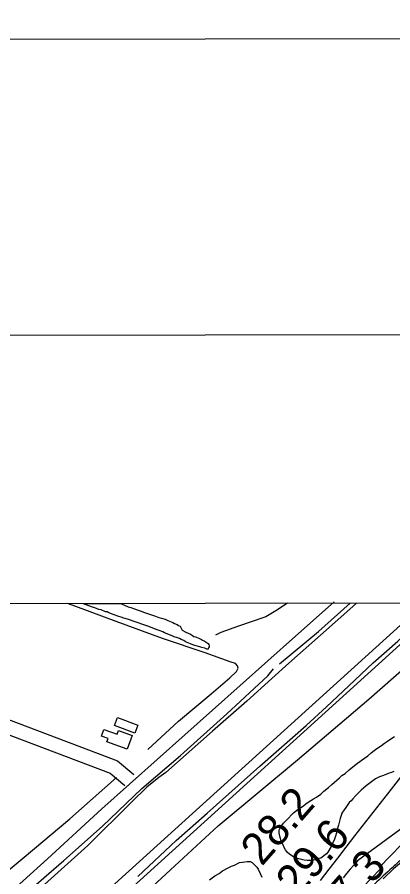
# Model space of a CAD drawing. Extents: x 3324125 to 3362000, y 600753 to 626151.
# Drawn here: x 3334294 to 3335086, y 623752 to 625567 of the extents above; entities that cross this region are included whole.
import ezdxf

# ---------------------------------------------------------------- set-up
doc = ezdxf.new("R2010")
doc.units = 0
for name, color, linetype in [('G-ANNO-NPLT', 7, 'Continuous'), ('V-ANNO-SYMB', 7, 'Continuous'), ('V-BLDG-OTLN', 7, 'Continuous'), ('V-DTCH-CNTR', 7, 'Continuous'), ('V-FLOD-BASE', 7, 'Continuous'), ('V-GRID-FRAM', 7, 'Continuous'), ('V-LEVE-TOET', 7, 'Continuous'), ('V-RIVR-EDGE', 7, 'Continuous'), ('V-RIVR-RANG', 7, 'Continuous'), ('V-ROAD-CNTR', 7, 'Continuous'), ('V-RRAP-RVMT', 7, 'Continuous'), ('V-SITE-VEGE', 7, 'Continuous'), ('V-SURV-LINE', 7, 'Continuous'), ('V-TOPO-MAJR', 7, 'Continuous'), ('V-TOPO-MINR', 7, 'Continuous'), ('V-TOPO-SHOR', 7, 'Continuous')]:
    doc.layers.add(name, color=color, linetype=linetype)

msp = doc.modelspace()

# ---------------------------------------------------------------- linework, layer by layer
at = {"layer": 'G-ANNO-NPLT'}
msp.add_lwpolyline([(3324750.5, 601336.7), (3361417.2, 601400.7), (3361375, 625567.3), (3324708.4, 625503.3)], close=True, dxfattribs=at)
at = {"layer": 'V-ANNO-SYMB'}
msp.add_lwpolyline([(3327499.6, 601966.6), (3360582.7, 602024.3), (3360542.7, 624940.8), (3327459.6, 624883.1), (3327499.6, 601966.6)], dxfattribs=at)
at = {"layer": 'V-BLDG-OTLN'}
for points in [[(3334505.7, 624088.4), (3334548.9, 624072.1), (3334542.6, 624055.7), (3334499.5, 624072)], [(3334526.1, 624021.5), (3334483.4, 624036.9), (3334486, 624044.1), (3334472.1, 624049.1), (3334477.3, 624063.5), (3334505.3, 624053.4), (3334508.1, 624061), (3334536.6, 624050.7)]]:
    msp.add_lwpolyline(points, close=True, dxfattribs=at)
at = {"layer": 'V-DTCH-CNTR'}
msp.add_lwpolyline([(3334864.3, 624329.8), (3334839.5, 624313.6), (3334818.8, 624301), (3334814.7, 624299.6), (3334760.8, 624281.2), (3334723.5, 624268.4), (3334712.4, 624262.8)], dxfattribs=at)
at = {"layer": 'V-FLOD-BASE'}
msp.add_lwpolyline([(3334548.7, 623752.8), (3334629.3, 623828.7), (3334694.8, 623886.6), (3334805.7, 623986), (3334903.7, 624071.5), (3334946.6, 624111.3), (3334993.7, 624155.4), (3335045, 624203.7), (3335097.3, 624249.9), (3335164.8, 624312.5), (3335184.9, 624330.4)], dxfattribs=at)
at = {"layer": 'V-GRID-FRAM'}
msp.add_lwpolyline([(3328210, 624318.2), (3328233.8, 606134.5), (3359834, 606189.7), (3359794.3, 624373.3), (3328210, 624318.2)], dxfattribs=at)
at = {"layer": 'V-LEVE-TOET'}
for points in [[(3335009.6, 624330), (3334995.9, 624317.7), (3334934.1, 624262.2), (3334867.4, 624203.3), (3334831.6, 624171.1), (3334778.9, 624123.1), (3334706, 624059.6), (3334608, 623972.7), (3334592.8, 623961.8), (3334567.6, 623941.3), (3334535.5, 623909.6), (3334443.4, 623818.2), (3334331, 623717.1)], [(3334560.5, 623714.3), (3334617.6, 623766.9), (3334718.3, 623860.2), (3334885.2, 623999.3), (3335035.7, 624127.2), (3335145.4, 624223.5), (3335252.8, 624327.9), (3335255.7, 624330.5)]]:
    msp.add_lwpolyline(points, dxfattribs=at)
at = {"layer": 'V-RIVR-EDGE'}
msp.add_spline([(3335799.7, 624331.4), (3335798.3, 624329.3), (3335794.2, 624318), (3335789.1, 624311.4), (3335780.7, 624303.1), (3335767.1, 624285.2), (3335747.7, 624260.7), (3335731.9, 624240.7), (3335698.2, 624211.1), (3335677.3, 624192.2), (3335662.7, 624176.5), (3335646.5, 624160.8), (3335632.3, 624145.9), (3335615.8, 624131.3), (3335603.3, 624120), (3335592.3, 624106.9), (3335585, 624096.6), (3335578.8, 624094.5), (3335568.5, 624087.9), (3335560.1, 624081), (3335551.6, 624071.1), (3335543.6, 624065.3), (3335538.1, 624063.5), (3335533, 624059.1), (3335530.8, 624053.6), (3335527.8, 624050.7), (3335522.7, 624050), (3335516.1, 624049.7), (3335512.5, 624049.3), (3335497.5, 624037.6), (3335485.4, 624029.3), (3335478.4, 624027.1), (3335472.9, 624023.8), (3335468.5, 624020.5), (3335461.2, 624015.1), (3335455, 624014.4), (3335451.7, 624013.6), (3335449.5, 624010.7), (3335449.5, 624008.2), (3335450.2, 624006.3), (3335449.1, 624003), (3335446.9, 624002.3), (3335438.2, 624001.6), (3335427.5, 623996.9), (3335420.2, 623992.9), (3335409.6, 623985.2), (3335401.9, 623977.9), (3335392.7, 623968.4), (3335375.5, 623956.1), (3335352.8, 623941.9), (3335330.9, 623930.2), (3335312.6, 623925.9), (3335303.4, 623923.7), (3335298.3, 623921.5), (3335294.3, 623916.4), (3335290.6, 623913.9), (3335277.5, 623909.9), (3335265.4, 623904.4), (3335244.1, 623893.5), (3335232.4, 623886.6), (3335209, 623874.2), (3335181.9, 623858.6), (3335164.7, 623847.3), (3335147.9, 623833.1), (3335127, 623810.5), (3335107.2, 623791.5), (3335089.6, 623775.5), (3335053, 623741.5), (3335042, 623729.5), (3335028.8, 623711.3), (3335018.1, 623697.8), (3335015.6, 623695.6), (3335013.4, 623695.2), (3335009, 623694.1), (3335004.6, 623690.5), (3334995.8, 623678.5), (3334991.7, 623671.9), (3334991.4, 623666), (3334990.6, 623658.4), (3334993.5, 623650.7), (3334993.9, 623647.7), (3334996.4, 623642.6), (3334993.1, 623636.8), (3334983.6, 623621.5), (3334967.1, 623601.8), (3334950.9, 623585), (3334929, 623567.9)], degree=3, dxfattribs=at)
at = {"layer": 'V-ROAD-CNTR'}
for points in [[(3334962.6, 624333), (3334881.1, 624260.2), (3334472.9, 623895.9), (3334358, 623790.3), (3334255.1, 623697.1), (3334200.7, 623647.7), (3334152.3, 623600.3), (3334077.2, 623518.6), (3333606.7, 622932.8), (3332948.8, 622115.4), (3332638.7, 621722.9), (3332601.1, 621669.5), (3332582.1, 621643.4), (3332550.9, 621581.9), (3332533.2, 621530.4), (3332516.7, 621467.3), (3332503.8, 621368.2), (3332484.7, 621134.9), (3332435.8, 620389.6)], [(3333436.2, 624344.7), (3333693.9, 624268.2), (3333748.7, 624256.7), (3333781.2, 624250.2), (3333823.7, 624243.1), (3333872.8, 624237.5), (3333917.3, 624219.9), (3334505.5, 623997.4), (3334540.5, 623967.9)], [(3333427.7, 624316), (3333686.6, 624239.1), (3333742.7, 624227.3), (3333775.8, 624220.7), (3333819.5, 624213.3), (3333865.5, 624208.1), (3333906.5, 624191.9), (3334490.1, 623971.2), (3334521.2, 623945)]]:
    msp.add_lwpolyline(points, dxfattribs=at)
at = {"layer": 'V-RRAP-RVMT'}
for p, q in [((3335168.6, 623886.4), (3335057.5, 623771.9)), ((3335060.2, 623769.4), (3334967.1, 623672.5)), ((3335057.5, 623771.9), (3335060.2, 623769.4))]:
    msp.add_line(p, q, dxfattribs=at)
at = {"layer": 'V-SITE-VEGE'}
for p, q in [((3334433.1, 624329), (3334512.9, 624329.2)), ((3334434.2, 624328.7), (3334433.1, 624329)), ((3334445.4, 624324.5), (3334434.2, 624328.7)), ((3334450.7, 624322.4), (3334445.4, 624324.5)), ((3334458.1, 624320.4), (3334450.7, 624322.4)), ((3334466.7, 624316.7), (3334458.1, 624320.4)), ((3334471.5, 624315.7), (3334466.7, 624316.7)), ((3334480.5, 624312), (3334471.5, 624315.7)), ((3334512.9, 624329.2), (3334514.4, 624328.7)), ((3334514.4, 624328.7), (3334528.3, 624322.5)), ((3334528.3, 624322.5), (3334533.6, 624320.9)), ((3334533.6, 624320.9), (3334541.6, 624318.3)), ((3334541.6, 624318.3), (3334547.4, 624316.2)), ((3334547.4, 624316.2), (3334553.8, 624313.6)), ((3334553.8, 624313.6), (3334562.9, 624310.5)), ((3334483.7, 624311.5), (3334480.5, 624312)), ((3334487.4, 624309.4), (3334483.7, 624311.5)), ((3334493.3, 624307.3), (3334487.4, 624309.4)), ((3334497, 624305.8), (3334493.3, 624307.3)), ((3334508.8, 624301.6), (3334497, 624305.8)), ((3334513.5, 624300.6), (3334508.8, 624301.6)), ((3334518.9, 624298.5), (3334513.5, 624300.6)), ((3334526.9, 624296.4), (3334518.9, 624298.5)), ((3334533.3, 624293.8), (3334526.9, 624296.4)), ((3334562.9, 624310.5), (3334569.3, 624308.4)), ((3334569.3, 624308.4), (3334575.7, 624305.8)), ((3334575.7, 624305.8), (3334585.8, 624302.7)), ((3334585.8, 624302.7), (3334593.3, 624300.1)), ((3334593.3, 624300.1), (3334598.6, 624298)), ((3334598.6, 624298), (3334606, 624295.9)), ((3334606, 624295.9), (3334611.9, 624293.3)), ((3334538.6, 624292.2), (3334533.3, 624293.8)), ((3334570, 624281.3), (3334538.6, 624292.2)), ((3334589.2, 624274), (3334570, 624281.3)), ((3334611.9, 624293.3), (3334618.8, 624290.7)), ((3334618.8, 624290.7), (3334622.6, 624289.1)), ((3334622.6, 624289.1), (3334626.3, 624287)), ((3334626.3, 624287), (3334631.6, 624284.9)), ((3334631.6, 624284.9), (3334634.3, 624282.8)), ((3334634.3, 624282.8), (3334638, 624281.3)), ((3334638, 624281.3), (3334642.3, 624273.3)), ((3334594, 624272.4), (3334589.2, 624274)), ((3334601.4, 624269.8), (3334594, 624272.4)), ((3334605.2, 624267.7), (3334601.4, 624269.8)), ((3334621.2, 624260.9), (3334605.2, 624267.7)), ((3334625.4, 624258.9), (3334621.2, 624260.9)), ((3334632.4, 624256.8), (3334625.4, 624258.9)), ((3334642.3, 624273.3), (3334649.8, 624268.6)), ((3334649.8, 624268.6), (3334655.1, 624266.5)), ((3334655.1, 624266.5), (3334659.9, 624264.4)), ((3334659.9, 624264.4), (3334664.2, 624261.8)), ((3334664.2, 624261.8), (3334666.9, 624259.7)), ((3334666.9, 624259.7), (3334670.1, 624259.2)), ((3334670.1, 624259.2), (3334672.2, 624258.1)), ((3334672.2, 624258.1), (3334678.6, 624255.5)), ((3334636.6, 624255.2), (3334632.4, 624256.8)), ((3334640.4, 624253.6), (3334636.6, 624255.2)), ((3334645.7, 624251), (3334640.4, 624253.6)), ((3334649.4, 624248.4), (3334645.7, 624251)), ((3334659.6, 624244.2), (3334649.4, 624248.4)), ((3334664.9, 624242.1), (3334659.6, 624244.2)), ((3334669.1, 624240.6), (3334664.9, 624242.1)), ((3334679.8, 624238), (3334669.1, 624240.6)), ((3334678.6, 624255.5), (3334682.9, 624253.4)), ((3334682.9, 624253.4), (3334685, 624251.8)), ((3334685, 624251.8), (3334688.7, 624250.3)), ((3334688.7, 624250.3), (3334695.1, 624246.6)), ((3334695.1, 624246.6), (3334696.7, 624245)), ((3334696.7, 624245), (3334698.4, 624242.4)), ((3334698.4, 624242.4), (3334698.9, 624240.2)), ((3334698.9, 624240.2), (3334698.9, 624237.6)), ((3334683.5, 624236.4), (3334679.8, 624238)), ((3334689.9, 624234.9), (3334683.5, 624236.4)), ((3334694.2, 624232.8), (3334689.9, 624234.9)), ((3334696.8, 624232.8), (3334694.2, 624232.8)), ((3334697.9, 624235.5), (3334696.8, 624232.8)), ((3334698.9, 624237.6), (3334697.9, 624235.5)), ((3335075, 624038.9), (3335084.5, 624045.3)), ((3335084.5, 624045.3), (3335090.3, 624048.5)), ((3335046.9, 624019), (3335052.8, 624023.3)), ((3335052.8, 624023.3), (3335062.3, 624029.7)), ((3335062.3, 624029.7), (3335069.2, 624034.6)), ((3335069.2, 624034.6), (3335075, 624038.9)), ((3335020, 623998.1), (3335033.7, 624007.8)), ((3335033.7, 624007.8), (3335041.1, 624014.2)), ((3335041.1, 624014.2), (3335046.9, 624019)), ((3334994.6, 623978.2), (3335009.4, 623990)), ((3335009.4, 623990), (3335020, 623998.1)), ((3334979.3, 623965.9), (3334985.7, 623970.2)), ((3334985.7, 623970.2), (3334994.6, 623978.2)), ((3335078.6, 623970.9), (3335070.7, 623967.6)), ((3335083.9, 623972.5), (3335078.6, 623970.9)), ((3335088.7, 623974.7), (3335083.9, 623972.5)), ((3334957.7, 623947.2), (3334974, 623961.1)), ((3334974, 623961.1), (3334979.3, 623965.9)), ((3335050, 623959), (3335030.5, 623944.5)), ((3335058.5, 623963.3), (3335050, 623959)), ((3335064.9, 623965.5), (3335058.5, 623963.3)), ((3335070.7, 623967.6), (3335064.9, 623965.5)), ((3334934.4, 623926.8), (3334940.8, 623932.7)), ((3334940.8, 623932.7), (3334950.8, 623940.7)), ((3334950.8, 623940.7), (3334957.7, 623947.2)), ((3335019.4, 623934.9), (3335008.3, 623923.6)), ((3335024.7, 623939.7), (3335019.4, 623934.9)), ((3335030.5, 623944.5), (3335024.7, 623939.7)), ((3334905.9, 623908.5), (3334913.3, 623913.4)), ((3334913.3, 623913.4), (3334919.1, 623916.6)), ((3334919.1, 623916.6), (3334925.4, 623920.4)), ((3334925.4, 623920.4), (3334934.4, 623926.8)), ((3335002, 623917.2), (3334998.3, 623912.9)), ((3335008.3, 623923.6), (3335002, 623917.2)), ((3334877.3, 623887.6), (3334886.8, 623895.1)), ((3334886.8, 623895.1), (3334895.8, 623900.5)), ((3334895.8, 623900.5), (3334905.9, 623908.5)), ((3334987.2, 623898.5), (3334984.1, 623893.7)), ((3334989.9, 623902.8), (3334987.2, 623898.5)), ((3334994.6, 623909.2), (3334989.9, 623902.8)), ((3334998.3, 623912.9), (3334994.6, 623909.2)), ((3334862, 623872.1), (3334877.3, 623887.6)), ((3334977.3, 623881.4), (3334975.7, 623875.6)), ((3334979.3, 623886.7), (3334977.3, 623881.4)), ((3334984.1, 623893.7), (3334979.3, 623886.7)), ((3334850.4, 623857.7), (3334856.2, 623865.7)), ((3334856.2, 623865.7), (3334862, 623872.1)), ((3334971.6, 623861.2), (3334969.5, 623854.8)), ((3334973.1, 623867), (3334971.6, 623861.2)), ((3334975.7, 623875.6), (3334973.1, 623867)), ((3334846.8, 623849.7), (3334847.8, 623852.9)), ((3334846.8, 623844.9), (3334846.8, 623849.7)), ((3334847.9, 623838), (3334846.8, 623844.9)), ((3334847.8, 623852.9), (3334850.4, 623857.7)), ((3334967.4, 623845.2), (3334965.3, 623838.3)), ((3334969.5, 623854.8), (3334967.4, 623845.2)), ((3334849.5, 623833.2), (3334847.9, 623838)), ((3334851.2, 623827.4), (3334849.5, 623833.2)), ((3334855, 623819.4), (3334851.2, 623827.4)), ((3334963.3, 623831.9), (3334956.5, 623816.4)), ((3334965.3, 623838.3), (3334963.3, 623831.9)), ((3334857.1, 623814.1), (3334855, 623819.4)), ((3334859.8, 623809.4), (3334857.1, 623814.1)), ((3334864.6, 623803.6), (3334859.8, 623809.4)), ((3334956.5, 623816.4), (3334949.1, 623804.2)), ((3334868.9, 623799.9), (3334864.6, 623803.6)), ((3334873.2, 623796.7), (3334868.9, 623799.9)), ((3334880.7, 623792.5), (3334873.2, 623796.7)), ((3334891.3, 623789.4), (3334880.7, 623792.5)), ((3334899.8, 623787.3), (3334891.3, 623789.4)), ((3334905.7, 623786.9), (3334899.8, 623787.3)), ((3334915.8, 623786.9), (3334905.7, 623786.9)), ((3334919.5, 623787.5), (3334915.8, 623786.9)), ((3334924.3, 623788), (3334919.5, 623787.5)), ((3334926.9, 623789.7), (3334924.3, 623788)), ((3334930.1, 623790.7), (3334926.9, 623789.7)), ((3334934.9, 623791.8), (3334930.1, 623790.7)), ((3334937.5, 623793.5), (3334934.9, 623791.8)), ((3334943.8, 623798.3), (3334937.5, 623793.5)), ((3334946.5, 623801), (3334943.8, 623798.3)), ((3334949.1, 623804.2), (3334946.5, 623801))]:
    msp.add_line(p, q, dxfattribs=at)
msp.add_lwpolyline([(3334699.8, 623745.5), (3334711.4, 623754.1), (3334719.9, 623759.5), (3334727.3, 623764.9), (3334738.9, 623771.3), (3334746.3, 623774.6), (3334752.7, 623776.7), (3334763.3, 623782.1), (3334769.7, 623783.2), (3334779.2, 623784.4), (3334785.6, 623784.4), (3334789.9, 623782.3), (3334799.5, 623772.8), (3334802.7, 623768.6), (3334807, 623759), (3334810.3, 623751.6)], dxfattribs=at)
at = {"layer": 'V-SURV-LINE'}
for points in [[(3334202, 623467.9), (3335154.4, 624330.4)], [(3335199.1, 624330.5), (3334222.2, 623445.6)]]:
    msp.add_lwpolyline(points, dxfattribs=at)
at = {"layer": 'V-TOPO-MAJR'}
msp.add_lwpolyline([(3335392.7, 624330.7), (3335310.3, 624226.6), (3335253.2, 624154.4), (3335196.2, 624082), (3335139.4, 624009.5), (3335082.7, 623937), (3335005.8, 623838.4), (3334987.6, 623815), (3334969.5, 623791.6), (3334951.5, 623768.2), (3334933.5, 623744.7)], dxfattribs=at)
at = {"layer": 'V-TOPO-MINR'}
for points in [[(3335724.5, 624331.3), (3335643, 624249.7), (3335639.5, 624246.7), (3335636, 624243.7), (3335632.4, 624240.8), (3335628.8, 624238), (3335625, 624235.3), (3335621.3, 624232.6), (3335617.4, 624230), (3335613.6, 624227.5), (3335012, 623785.9), (3335004.2, 623777), (3334996.5, 623768.1), (3334989.1, 623758.9), (3334981.7, 623749.7)], [(3335756.6, 624331.4), (3335679.8, 624262.7), (3335672.5, 624255.7), (3335665.1, 624248.8), (3335657.7, 624242), (3335650.2, 624235.2), (3335622, 624210.2), (3335604.8, 624195.2), (3335587.4, 624180.4), (3335569.6, 624166), (3335551.7, 624151.9), (3335533.5, 624138), (3335515.3, 624124.3), (3335087.9, 623769), (3335066.1, 623747.7)]]:
    msp.add_lwpolyline(points, dxfattribs=at)
at = {"layer": 'V-TOPO-SHOR'}
for points in [[(3334570.1, 624021), (3334634.5, 624081), (3334703.7, 624138.9), (3334742.8, 624172.6), (3334756.5, 624186), (3334760.1, 624193), (3334759, 624197.7), (3334754.8, 624202.5), (3334743.6, 624206.1), (3334690.8, 624225.4), (3334600.8, 624255.1), (3334503.3, 624291), (3334418.1, 624322.8), (3334400.6, 624329)], [(3334847.3, 624201.6), (3334930, 624270), (3334996.5, 624330)], [(3333745.4, 623072.5), (3333817.9, 623161.4), (3333916.9, 623286.3), (3334006, 623390.6), (3334080.3, 623484.7), (3334173.1, 623584.5), (3334227.9, 623637.1), (3334292.4, 623699.1), (3334392.8, 623786.3), (3334474.3, 623859.2), (3334557.2, 623938.9), (3334638.8, 624008.4), (3334736.6, 624096), (3334822.9, 624176.8), (3334835.1, 624191.4)], [(3334015.7, 623515.4), (3334053.7, 623556.6), (3334110.2, 623614.4), (3334166.6, 623670.6), (3334241.1, 623738.1), (3334309.2, 623793.9), (3334405.3, 623874.8), (3334503.5, 623962.1)]]:
    msp.add_lwpolyline(points, dxfattribs=at)

# ---------------------------------------------------------------- texts
at = {"layer": 'V-RIVR-RANG'}
for s, p in [('28.2', (3334810.2, 623772.9)), ('29.6', (3334884.4, 623705.8)), ('17.3', (3334961, 623641.5))]:
    msp.add_text(s, height=67, rotation=48.7683, dxfattribs=at).set_placement(p)

doc.saveas('drawing.dxf')
